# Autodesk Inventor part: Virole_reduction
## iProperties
Shininess: 64.0
Length Units: 11269
Angle Units: 11279
Time Units: 11290
Mass Units: 11283
Length Display Precision: 3
Angle Display Precision: 2
Compacted: True
Part Number: Virole_reduction
Document SubType Name: Modeling
Created: 2008-04
Material: Par défaut
Designer: plup
Density: 0.0
Volumn: 0.0
Area: 0.0
PropertySet Name: Model Information
Control State: 0
Master: False
Checked Out: False
MATIERE_PIECE: X2CrNi 18-11
OBSERVATIONS: Tube Ø..
DESIGNATION: Manchon
Author: plup
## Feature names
1. Extrusion1
2. Extrusion2
